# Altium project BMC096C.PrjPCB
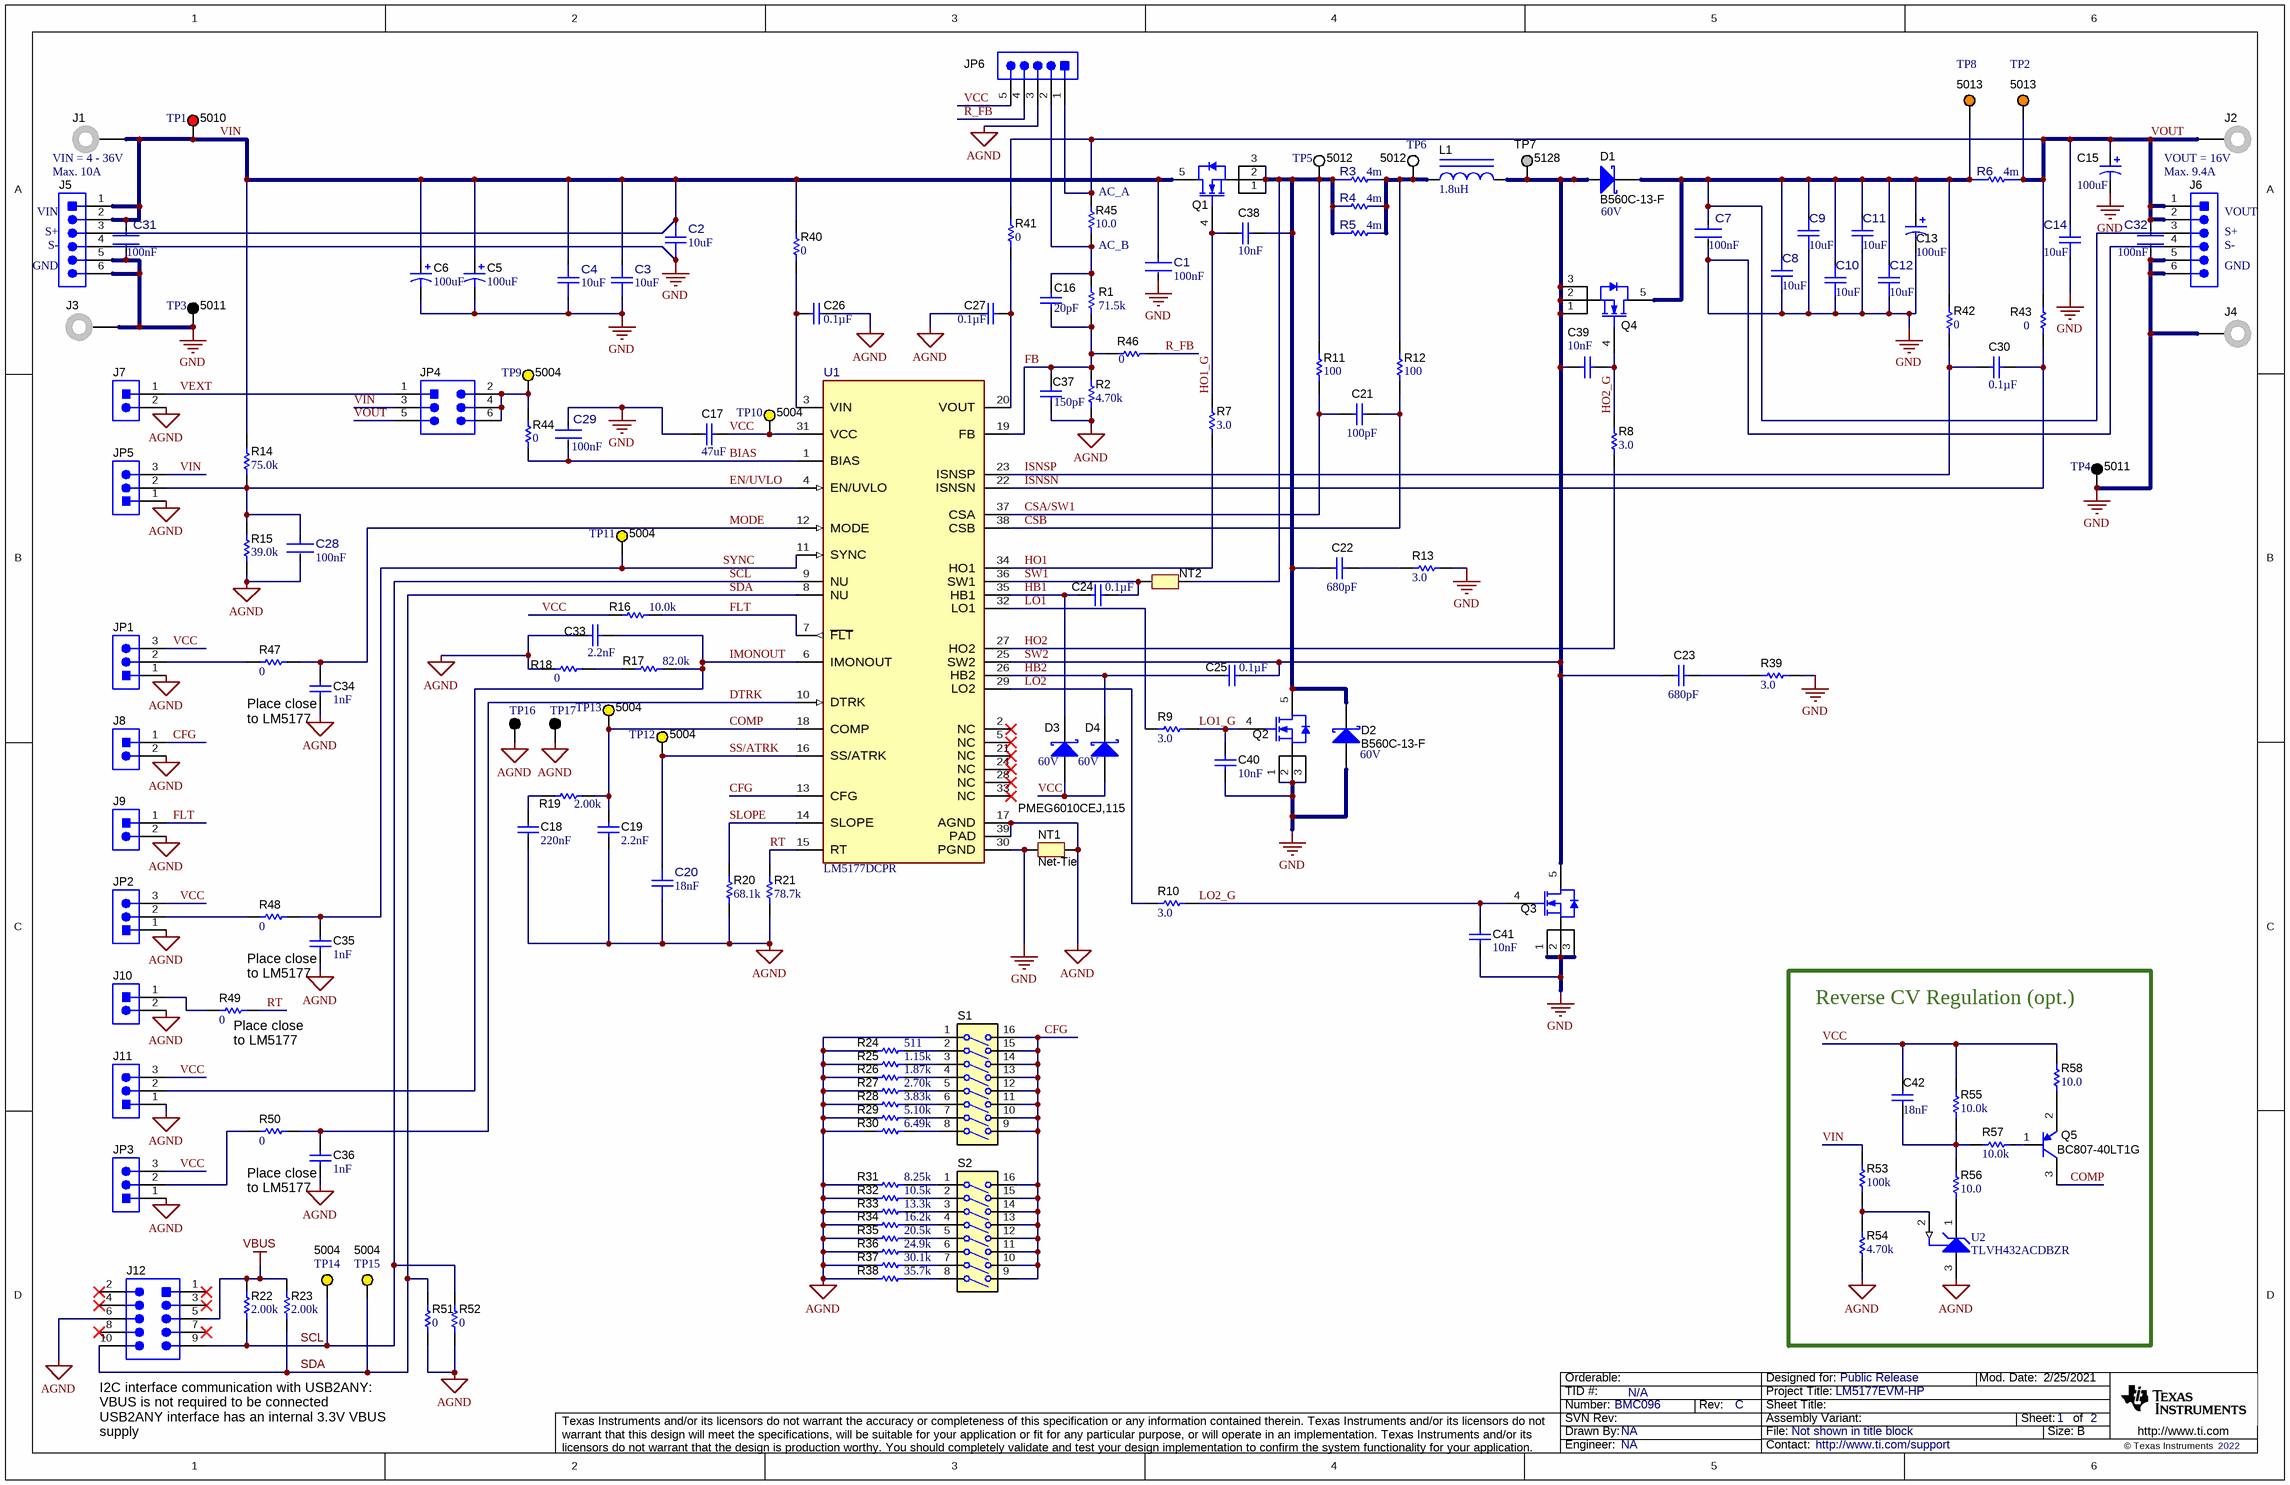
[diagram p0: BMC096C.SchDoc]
TID: N/A; TechSupport: http://www.ti.com/support; SCH_Rev: C; PRJ_Title: LM5177EVM-HP; PRJ_Number: BMC096; PRJ_Engineer: NA; PRJ_Customer: Public Release; PCB_Rev: C; PCB_Layout: NA; CopyrightYear: 2022
2 sheets, 175 parts. Net scope: global (net labels, ports and power ports of the same name join across sheets).
Board file: BMC096C.PcbDoc
Sheets:
  BMC096C.SchDoc
  BMC096C_Hardware.SchDoc

## Sheet BMC096C.SchDoc
size 431 x 279 mm; Date: Not shown in title block; ApprovedBy: Not shown in title block; CheckedBy: Not shown in title block; Author: Not shown in title block; CompanyName: Not shown in title block; DrawnBy: NA; Engineer: Not shown in title block; Organization: Not shown in title block; Address1: Not shown in title block; Address2: Not shown in title block; Address3: Not shown in title block; Address4: Not shown in title block; DocumentNumber: 2; Revision: Use project parameter SCH_Rev; SheetNumber: 1; SheetTotal: 2; PageSetup: Record=PageOptions¦CenterHorizontal=True¦CenterVertical=True¦PrintScale=1.00¦XCorrection=1.00¦YCorrection=1.00¦PrintKind=0¦BorderSize=5000000¦LeftOffset=0¦BottomOffset=0¦Orientation=2¦PaperLength=1000¦PaperWidth=1000¦Scale=100¦PaperSource=15¦PrintQuality=600¦MediaType=1¦DitherType=10¦PaperKind=Letter¦PrintScaleMode=1

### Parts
C1  Cap_F: 100nF  [FP-GCM188L81H104KA57D_0603-MFG]  (hidden comment: GCM188L81H104KA57D)
C2  ValueDisplayed: 10uF  [FP-GCM32EC71H106KA03L_1210-MFG]  (hidden comment: GCM32EC71H106KA03L)
C3  ValueDisplayed: 10uF  [FP-GCM32EC71H106KA03L_1210-MFG]  (hidden comment: GCM32EC71H106KA03L)
C4  ValueDisplayed: 10uF  [FP-GCM32EC71H106KA03L_1210-MFG]  (hidden comment: GCM32EC71H106KA03L)
C5  ValueDisplayed: 100uF  [CR_1000x1270]  (hidden comment: PCR1J101MCL1GS)
C6  ValueDisplayed: 100uF  [CR_1000x1270]  (hidden comment: PCR1J101MCL1GS)
C7  Cap_F: 100nF  [FP-GCM188L81H104KA57D_0603-MFG]  (hidden comment: GCM188L81H104KA57D)
C8  ValueDisplayed: 10uF  [FP-GCM32EC71H106KA03L_1210-MFG]  (hidden comment: GCM32EC71H106KA03L)
C9  ValueDisplayed: 10uF  [FP-GCM32EC71H106KA03L_1210-MFG]  (hidden comment: GCM32EC71H106KA03L)
C10  ValueDisplayed: 10uF  [FP-GCM32EC71H106KA03L_1210-MFG]  (hidden comment: GCM32EC71H106KA03L)
C11  ValueDisplayed: 10uF  [FP-GCM32EC71H106KA03L_1210-MFG]  (hidden comment: GCM32EC71H106KA03L)
C12  ValueDisplayed: 10uF  [FP-GCM32EC71H106KA03L_1210-MFG]  (hidden comment: GCM32EC71H106KA03L)
C13  ValueDisplayed: 100uF  [CR_1000x1270]  (hidden comment: PCR1J101MCL1GS)
C14  ValueDisplayed: 10uF  [FP-GCM32EC71H106KA03L_1210-MFG]  (hidden comment: GCM32EC71H106KA03L)
C15  ValueDisplayed: 100uF  [CR_1000x1270]  (hidden comment: PCR1J101MCL1GS)
C16  ValueDisplayed: 20pF  [0603S]  (hidden comment: GRM1885C2A200JA01D)
C17  ValueDisplayed: 47uF  [0603S]  (hidden comment: GRM188R60J476ME15D)
C18  Cap_F: 220nF  [0603S]  (hidden comment: CGA3E3X7R1H224K080AB)
C19  Cap_F: 2.2nF  [0603S]  (hidden comment: 06031C222JAT2A)
C20  ValueDisplayed: 18nF  [FP-GCM21B5C1H183JA16L_0805-MFG]  (hidden comment: GCM21B5C1H183JA16L)
C21  ValueDisplayed: 100pF  [0603S]  (hidden comment: GCM1885C1H101JA16J)
C22  ValueDisplayed: 680pF  [0805_HV1]  (hidden comment: GRM2165C1H681JA01D)
C23  ValueDisplayed: 680pF  [0805_HV1]  (hidden comment: GRM2165C1H681JA01D)
C24  ValueDisplayed: 0.1µF  [0402S]  (hidden comment: 0402BB104KW500)
C25  ValueDisplayed: 0.1µF  [0402S]  (hidden comment: 0402BB104KW500)
C26  ValueDisplayed: 0.1µF  [0402S]  (hidden comment: 0402BB104KW500)
C27  ValueDisplayed: 0.1µF  [0402S]  (hidden comment: 0402BB104KW500)
C28  Cap_F: 100nF  [FP-GCM188L81H104KA57D_0603-MFG]  (hidden comment: GCM188L81H104KA57D)
C29  Cap_F: 100nF  [FP-GCM188L81H104KA57D_0603-MFG]  (hidden comment: GCM188L81H104KA57D)
C30  ValueDisplayed: 0.1µF  [0402S]  (hidden comment: 0402BB104KW500)
C31  Cap_F: 100nF  [FP-GCM188L81H104KA57D_0603-MFG]  (hidden comment: GCM188L81H104KA57D)
C32  Cap_F: 100nF  [FP-GCM188L81H104KA57D_0603-MFG]  (hidden comment: GCM188L81H104KA57D)
C33  Cap_F: 2.2nF  [0603S]  (hidden comment: 06031C222JAT2A)
C34  Cap_F: 1nF  [0603S]  (hidden comment: 06031C102JAT2A)
C35  Cap_F: 1nF  [0603S]  (hidden comment: 06031C102JAT2A)
C36  Cap_F: 1nF  [0603S]  (hidden comment: 06031C102JAT2A)
C37  ValueDisplayed: 150pF  [0603S]  (hidden comment: GRM1885C1H151JA01D)
C38  Cap_F: 10nF  [0603S]  (hidden comment: GRM188R72A103KA01D)
C39  Cap_F: 10nF  [0603S]  (hidden comment: GRM188R72A103KA01D)
C40  Cap_F: 10nF  [0603S]  (hidden comment: GRM188R72A103KA01D)
C41  Cap_F: 10nF  [0603S]  (hidden comment: GRM188R72A103KA01D)
C42  Cap_F: 18nF  [0603S]  (hidden comment: C0603C183K1RACTU)
D1  B560C-13-F  value 60V  [SMC]
D2  B560C-13-F  value 60V  [SMC]
D3  value 60V  [SOD-323F]  (hidden comment: PMEG6010CEJ,115)
D4  PMEG6010CEJ,115  value 60V  [SOD-323F]
J1  108-0740-001  [Johnson_108-0740-001]  (value not drawn)
J2  108-0740-001  [Johnson_108-0740-001]  (value not drawn)
J3  108-0740-001  [Johnson_108-0740-001]  (value not drawn)
J4  108-0740-001  [Johnson_108-0740-001]  (value not drawn)
J5  61300611121  [WURTH_61300611121]  (value not drawn)
J6  61300611121  [WURTH_61300611121]  (value not drawn)
J7  61300211121  [WURTH_61300211121]  (value not drawn)
J8  61300211121  [WURTH_61300211121]  (value not drawn)
J9  61300211121  [WURTH_61300211121]  (value not drawn)
J10  61300211121  [WURTH_61300211121]  (value not drawn)
J11  61300311121  [WURTH_61300311121]  (value not drawn)
J12  N2510-6002-RB  [CONN_2510-6002]  (value not drawn)
JP1  61300311121  [WURTH_61300311121]  (value not drawn)
JP2  61300311121  [WURTH_61300311121]  (value not drawn)
JP3  61300311121  [WURTH_61300311121]  (value not drawn)
JP4  HTSW-103-07-G-D  [Samtec_HTSW-103-07-x-D]  (value not drawn)
JP5  61300311121  [WURTH_61300311121]  (value not drawn)
JP6  61300511121  [Wurth_61300511121]  (value not drawn)
L1  ValueDisplayed: 1.8uH  [IHLP-5050FD]  (hidden comment: IHLP5050FDER1R8M01)
NT1  Net-Tie  [Net-Tie_10mil]  (net tie, no BOM)
NT2  Net-Tie  [Net-Tie_20milWide_60milLong]  (value not drawn)  (net tie, no BOM)
Q1  SQJ422EP-T1-GE3  [PowerPAK_SO-8L]  (value not drawn)
Q2  SQJ422EP-T1-GE3  [PowerPAK_SO-8L]  (value not drawn)
Q3  SQJ422EP-T1-GE3  [PowerPAK_SO-8L]  (value not drawn)
Q4  SQJ422EP-T1-GE3  [PowerPAK_SO-8L]  (value not drawn)
Q5  BC807-40LT1G  [SOT-23]
R1  ValueDisplayed: 71.5k  [0603S]  (hidden comment: RC0603FR-0771K5L)
R2  ValueDisplayed: 4.70k  [0603S]  (hidden comment: RC0603FR-074K7L)
R3  value 4m  [FP-KRL2012E-M-R004-F-T5_2012-MFG]  (hidden comment: KRL2012E-M-R004-F-T5)
R4  value 4m  [FP-KRL2012E-M-R004-F-T5_2012-MFG]  (hidden comment: KRL2012E-M-R004-F-T5)
R5  value 4m  [FP-KRL2012E-M-R004-F-T5_2012-MFG]  (hidden comment: KRL2012E-M-R004-F-T5)
R6  value 4m  [FP-KRL2012E-M-R004-F-T5_2012-MFG]  (hidden comment: KRL2012E-M-R004-F-T5)
R7  ValueDisplayed: 3.0  [0603S]  (hidden comment: CRCW06033R00JNEA)
R8  ValueDisplayed: 3.0  [0603S]  (hidden comment: CRCW06033R00JNEA)
R9  ValueDisplayed: 3.0  [0603S]  (hidden comment: CRCW06033R00JNEA)
R10  ValueDisplayed: 3.0  [0603S]  (hidden comment: CRCW06033R00JNEA)
R11  ValueDisplayed: 100  [0603S]  (hidden comment: CRCW0603100RFKEAHP)
R12  ValueDisplayed: 100  [0603S]  (hidden comment: CRCW0603100RFKEAHP)
R13  ValueDisplayed: 3.0  [0603S]  (hidden comment: CRCW06033R00JNEA)
R14  ValueDisplayed: 75.0k  [0603S]  (hidden comment: RC0603FR-0775KL)
R15  ValueDisplayed: 39.0k  [0603S]  (hidden comment: RC0603FR-0739KL)
R16  ValueDisplayed: 10.0k  [0603S]  (hidden comment: RT0603BRD0710KL)
R17  ValueDisplayed: 82.0k  [0603S]  (hidden comment: RC0603FR-0782KL)
R18  ValueDisplayed: 0  [0603S]  (hidden comment: RMCF0603ZT0R00)
R19  ValueDisplayed: 2.00k  [0603S]  (hidden comment: RC0603FR-072KL)
R20  ValueDisplayed: 68.1k  [0603S]  (hidden comment: CRCW060368K1FKEA)
R21  ValueDisplayed: 78.7k  [0603S]  (hidden comment: RC0603FR-0778K7L)
R22  ValueDisplayed: 2.00k  [0603S]  (hidden comment: RC0603FR-072KL)
R23  ValueDisplayed: 2.00k  [0603S]  (hidden comment: RC0603FR-072KL)
R24  ValueDisplayed: 511  [0603S]  (hidden comment: CRCW0603511RFKEA)
R25  ValueDisplayed: 1.15k  [0603S]  (hidden comment: CRCW06031K15FKEA)
R26  ValueDisplayed: 1.87k  [0603S]  (hidden comment: RC0603FR-071K87L)
R27  ValueDisplayed: 2.70k  [0603S]  (hidden comment: RC0603FR-072K7L)
R28  ValueDisplayed: 3.83k  [0603S]  (hidden comment: CRCW06033K83FKEA)
R29  ValueDisplayed: 5.10k  [0603S]  (hidden comment: RC0603FR-075K1L)
R30  ValueDisplayed: 6.49k  [0603S]  (hidden comment: RC0603FR-076K49L)
R31  ValueDisplayed: 8.25k  [0603S]  (hidden comment: RC0603FR-078K25L)
R32  ValueDisplayed: 10.5k  [0603S]  (hidden comment: CRCW060310K5FKEA)
R33  ValueDisplayed: 13.3k  [0603S]  (hidden comment: RC0603FR-0713K3L)
R34  ValueDisplayed: 16.2k  [0603S]  (hidden comment: CRCW060316K2FKEA)
R35  ValueDisplayed: 20.5k  [0603S]  (hidden comment: RC0603FR-0720K5L)
R36  ValueDisplayed: 24.9k  [0603S]  (hidden comment: CRCW060324K9FKEA)
R37  ValueDisplayed: 30.1k  [0603S]  (hidden comment: CRCW060330K1FKEA)
R38  ValueDisplayed: 35.7k  [0603S]  (hidden comment: CRCW060335K7FKEA)
R39  ValueDisplayed: 3.0  [0603S]  (hidden comment: CRCW06033R00JNEA)
R40  ValueDisplayed: 0  [0603S]  (hidden comment: RMCF0603ZT0R00)
R41  ValueDisplayed: 0  [0603S]  (hidden comment: RMCF0603ZT0R00)
R42  ValueDisplayed: 0  [0603S]  (hidden comment: RMCF0603ZT0R00)
R43  ValueDisplayed: 0  [0603S]  (hidden comment: RMCF0603ZT0R00)
R44  ValueDisplayed: 0  [0603S]  (hidden comment: RMCF0603ZT0R00)
R45  ValueDisplayed: 10.0  [0603S]  (hidden comment: RC0603FR-0710RL)
R46  ValueDisplayed: 0  [0603S]  (hidden comment: RMCF0603ZT0R00)
R47  ValueDisplayed: 0  [0603S]  (hidden comment: RMCF0603ZT0R00)
R48  ValueDisplayed: 0  [0603S]  (hidden comment: RMCF0603ZT0R00)
R49  ValueDisplayed: 0  [0603S]  (hidden comment: RMCF0603ZT0R00)
R50  ValueDisplayed: 0  [0603S]  (hidden comment: RMCF0603ZT0R00)
R51  ValueDisplayed: 0  [0603S]  (hidden comment: RMCF0603ZT0R00)
R52  ValueDisplayed: 0  [0603S]  (hidden comment: RMCF0603ZT0R00)
R53  ValueDisplayed: 100k  [0603S]  (hidden comment: RC0603FR-07100KL)
R54  ValueDisplayed: 4.70k  [0603S]  (hidden comment: RC0603FR-074K7L)
R55  ValueDisplayed: 10.0k  [0603S]  (hidden comment: CRCW060310K0FKEA)
R56  ValueDisplayed: 10.0  [0603S]  (hidden comment: RC0603FR-0710RL)
R57  ValueDisplayed: 10.0k  [0603S]  (hidden comment: CRCW060310K0FKEA)
R58  ValueDisplayed: 10.0  [0603S]  (hidden comment: RC0603FR-0710RL)
S1  218-8LPST  [SW_218-8LP]  (value not drawn)
S2  218-8LPST  [SW_218-8LP]  (value not drawn)
TP1  5010  [Keystone5010]
TP2  5013  [Keystone5013]
TP3  5011  [Keystone5011]
TP4  5011  [Keystone5011]
TP5  5012  [Keystone5012]
TP6  5012  [Keystone5012]
TP7  5128  [Keystone5128]
TP8  5013  [Keystone5013]
TP9  5004  [Keystone5004]
TP10  5004  [Keystone5004]
TP11  5004  [Keystone5004]
TP12  5004  [Keystone5004]
TP13  5004  [Keystone5004]
TP14  5004  [Keystone5004]
TP15  5004  [Keystone5004]
TP16  5001  [Keystone5001]  (value not drawn)
TP17  5001  [Keystone5001]  (value not drawn)
U1  LM5177DCPR  [DCP0038A-MFG]
U2  TLVH432ACDBZR  [DBZ0003A_N]

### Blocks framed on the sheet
Reverse CV Regulation (opt.): C42 Q5 R53-R58 U2

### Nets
AGND: C18.2 C19.2 C20.1 C26.1 C27.2 C28.2 C33.1 C34.2 C35.2 C36.2 C37.2 J7.2 J8.2 J9.2 J10.2 J11.1 J12.6 JP1.1 JP2.1 JP3.1 JP5.1 JP6.3 NT1.2 R2.1 R15.1 R18.1 R20.1 R21.1 R24.1 R25.1 R26.1 R27.1 R28.1 R29.1 R30.1 R31.1 R32.1 R33.1 R34.1 R35.1 R36.1 R37.1 R38.1 R51.1 R52.1 R54.1 S1.1 TP16.1 TP17.1 U1.17(AGND) U1.39(PAD) U2.3(ANODE)
GND: C1.2 C2.1 C3.1 C4.1 C5.2(-) C6.2(-) C7.2 C8.1 C9.1 C10.1 C11.1 C12.1 C13.2(-) C14.1 C15.2(-) C17.1 C29.1 C31.2 C32.2 C40.1 C41.1 D2.2(A) J3.1 J4.1 J5.4 J5.5 J5.6 J6.4 J6.5 J6.6 NT1.1 Q2.1(S) Q2.2(S) Q2.3(S) Q3.1(S) Q3.2(S) Q3.3(S) R13.1 R39.1 TP3.1 TP4.1 U1.30(PGND)
VBUS: J12.5 R22.2 R23.2
BIAS: C29.2 R44.1 U1.1(BIAS)
CFG: J8.1 S1.9(8A) S1.10(7A) S1.11(6A) S1.12(5A) S1.13(4A) S1.14(3A) S1.15(2A) S1.16(1A) S2.9(8A) S2.10(7A) S2.11(6A) S2.12(5A) S2.13(4A) S2.14(3A) S2.15(2A) S2.16(1A) U1.13(CFG)
COMP: C19.1 Q5.3(C) R19.2 TP13.1 U1.18(COMP)
CSA/SW1: C21.2 R11.1 U1.37(CSA)
CSB: C21.1 R12.1 U1.38(CSB)
DTRK: C36.1 R50.2 U1.10(DTRK)
EN/UVLO: C28.1 JP5.2 R14.1 R15.2 U1.4(EN/UVLO)
FB: C16.2 C37.1 R1.2 R2.2 R46.1 U1.19(FB)
FLT: J9.1 R16.2 U1.7(~{FLT})
HB1: C24.2 D3.1(K) U1.35(HB1)
HB2: C25.2 D4.1(K) U1.26(HB2)
HO1: R7.1 U1.34(HO1)
HO1_G: C38.1 Q1.4(G) R7.2
HO2: R8.1 U1.27(HO2)
HO2_G: C39.2 Q4.4(G) R8.2
IMONOUT: C33.2 J11.2 R17.2 U1.6(IMONOUT)
ISNSN: C30.1 R43.1 U1.22(ISNSN)
ISNSP: C30.2 R42.1 U1.23(ISNSP)
LO1: R9.2 U1.32(LO1)
LO1_G: C40.2 Q2.4(G) R9.1
LO2: R10.2 U1.29(LO2)
LO2_G: C41.2 Q3.4(G) R10.1
MODE: C34.1 R47.2 U1.12(MODE)
R_FB: JP6.4 R46.2
RT: R21.2 R49.1 U1.15(RT)
SCL: J12.9 R22.1 R52.2 TP14.1 U1.9(NU)
SDA: J12.10 R23.1 R51.2 TP15.1 U1.8(NU)
SLOPE: R20.2 U1.14(SLOPE)
SS/ATRK: C20.2 TP12.1 U1.16(SS/ATRK)
SW1: C24.1 NT2.1 U1.36(SW1)
SW2: C23.2 C25.1 C39.1 D1.2(A) L1.2 Q3.5(D) Q4.1(S) Q4.2(S) Q4.3(S) TP7.1 U1.25(SW2)
SYNC: C35.1 R48.2 TP11.1 U1.11(SYNC)
VCC: C17.2 C42.1 D3.2(A) D4.2(A) J11.3 JP1.3 JP2.3 JP3.3 JP6.5 R16.1 R55.2 R58.1 TP10.1 U1.31(VCC)
VEXT: J7.1 JP4.1
VIN: C1.1 C2.2 C3.2 C4.2 C5.1(+) C6.1(+) C31.1 J1.1 J5.1 J5.2 J5.3 JP4.3 JP5.3 Q1.5(D) R14.2 R40.2 R53.2 TP1.1
VOUT: C14.2 C15.1(+) C32.1 J2.1 J6.1 J6.2 JP4.5 JP6.1 R6.2 R41.2 R43.2 R45.2 TP2.1
NetC7_1: C7.1 C8.2 C9.2 C10.2 C11.2 C12.2 C13.1(+) D1.1(K) J6.3 Q4.5(D) R6.1 R42.2 TP8.1
NetC16_1: C16.1 JP6.2 R1.1 R45.1
NetC18_1: C18.1 R19.1
NetC22_1: C22.1 R13.2
NetC22_2: C22.2 C38.2 D2.1(K) NT2.2 Q1.1(S) Q1.2(S) Q1.3(S) Q2.5(D) R3.1 R4.1 R5.1 R11.2 TP5.1
NetC23_1: C23.1 R39.2
NetC26_2: C26.2 R40.1 U1.3(VIN)
NetC27_1: C27.1 R41.1 U1.20(VOUT)
NetC42_2: C42.2 R55.1 R56.2 R57.2
NetJ10_1: J10.1 R49.2
NetJP1_2: JP1.2 R47.1
NetJP2_2: JP2.2 R48.1
NetJP3_2: JP3.2 R50.1
NetJP4_2: JP4.2 JP4.4 JP4.6 R44.2 TP9.1
NetL1_1: L1.1 R3.2 R4.2 R5.2 R12.2 TP6.1
NetQ5_1: Q5.1(B) R57.1
NetQ5_2: Q5.2(E) R58.2
NetR17_1: R17.1 R18.2
NetR24_2: R24.2 S1.2
NetR25_2: R25.2 S1.3
NetR26_2: R26.2 S1.4
NetR27_2: R27.2 S1.5
NetR28_2: R28.2 S1.6
NetR29_2: R29.2 S1.7
NetR30_2: R30.2 S1.8
NetR31_2: R31.2 S2.1
NetR32_2: R32.2 S2.2
NetR33_2: R33.2 S2.3
NetR34_2: R34.2 S2.4
NetR35_2: R35.2 S2.5
NetR36_2: R36.2 S2.6
NetR37_2: R37.2 S2.7
NetR38_2: R38.2 S2.8
NetR53_1: R53.1 R54.2 U2.2(REF)
NetR56_1: R56.1 U2.1(CATHODE)

Not connected (* = marked no-connect by the designer): J12 1* 2* 3* 4* 7* 8*; U1 2(NC)* 5(NC)* 21(NC)* 24(NC)* 28(NC)* 33(NC)*

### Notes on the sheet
- (near J1) VIN = 4 - 36V
- (near J2) VOUT = 16V
- (near J5) VIN
- Max. 10A
- (near R45) AC_A
- Max. 9.4A
- (near J6) VOUT
- (near J5) GND
- (near J5) S+
- (near J5) S-
- (near R45) AC_B
- (near J6) S+
- (near J6) S-
- (near J6) GND
- (near C34) Place close
  to LM5177
- (near C35) Place close
  to LM5177
- (near R49) Place close
  to LM5177
- (near C36) Place close
  to LM5177
- I2C interface communication with USB2ANY:
  VBUS is not required to be connected
  USB2ANY interface has an internal 3.3V VBUS supply

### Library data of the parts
C1 C7 C28 C29 C31 C32 = CMP-0086535-1: 0.1µF ±10% 50V Ceramic Capacitor X8L 0603 (1608 Metric); Manufacturer: Murata Electronics North America; Symbol Name: SYM-GCM188L81H104KA57D; AEC Qualified: Yes; TempCo: -40+15%; SizeZ_mm: 0.9mm; AEC Grade: Grade 0
C2-C4 C8-C12 C14 = CMP-0092251-1: Ceramic Capacitor for Automotive 10uF ±10% 50VDC X7S 1210 Embossed T/R; Manufacturer: Murata; AEC Grade: Grade 1; TempCo: 22%; AEC Qualified: Yes; VDC_V: 50V; Cap_F: 10µF; SizeZ_mm: 2.7mm; Value: 10µF
C5 C6 C13 C15 = CMP-0012274-3: CAP, Aluminum Polymer, 100 uF, 63 V, +/- 20%, 0.024 ohm, SMD, 2-Leads, Dia 10.5mm, Pin Spacing 8mm SMD; Manufacturer: Nichicon; TaMin_C: -55°C; ESR_ohm: 24m; Polarized: Y; Value: 100uF; TaMax_C: 125°C; Cap_Case: 10x12.7mm; Value2: 63V; CompType: Capacitor; AEC Qualified: N; Cap_F: 100µF; IRMS_A: 3A; AEC Category: Q200
C16 = CMP-0007253-4: CAP, CERM, 20 pF, 100 V, +/- 5%, C0G/NP0, 0603; Manufacturer: MuRata; TaMin_C: -55°C; Polarized: N; SizeAreaWB_mm2: 4.68; Value1: Unknown; U/M: EA; Value: 20pF; TaMax_C: 125°C; SizeZ_mm: 1; SizeX_mm: 1.6; SizeY_mm: 0.8; Cap_Case: 0603; Value2: 100V; SizeArea_mm2: 1.28; AEC Category: Q200
C17 = CMP-0007313-5: CAP, CERM, 47 uF, 6.3 V, +/- 20%, X5R, 0603; Manufacturer: MuRata; TaMin_C: -55°C; Polarized: N; SizeAreaWB_mm2: 4.68; Value1: Unknown; U/M: EA; Value: 47uF; TaMax_C: 85°C; SizeZ_mm: 1; SizeX_mm: 1.6; SizeY_mm: 0.8; Cap_Case: 0603; Value2: 6.3V; SizeArea_mm2: 1.28; Cap_F: 47µF; AEC Category: Q200
C18 = CMP-0007094-5: CAP, CERM, 0.22 uF, 50 V, +/- 10%, X7R, AEC-Q200 Grade 1, 0603; Manufacturer: TDK; TaMin_C: -55°C; ESR_ohm: 0.021699; Polarized: N; SizeAreaWB_mm2: 4.68; Value1: 0.021699 ohm; U/M: EA; Value: 0.22uF; TaMax_C: 125°C; SizeZ_mm: 1; SizeX_mm: 1.6; SizeY_mm: 0.8; Cap_Case: 0603; Value2: 50V; SizeArea_mm2: 1.28; AEC Qualified: Y; IRMS_A: 1.12496A; AEC Category: Q200
C19 C33 = CMP-0006736-4: CAP, CERM, 2200 pF, 100 V, +/- 5%, X7R, 0603; Manufacturer: AVX; TaMin_C: -55°C; ESR_ohm: 0.192; Polarized: N; SizeAreaWB_mm2: 4.68; Value1: 0.192 ohm; U/M: EA; Value: 2200pF; TaMax_C: 125°C; SizeZ_mm: 1; SizeX_mm: 1.6; SizeY_mm: 0.8; Cap_Case: 0603; Value2: 100V; SizeArea_mm2: 1.28; AEC Category: Q200
C20 = CMP-0092440-1: Ceramic Capacitor for Automotive 18nF ±5% 50VDC C0G 0805 Embossed T/R; Manufacturer: Murata; TempCo: 30ppm/°C; AEC Qualified: Yes; AEC Grade: Grade 1; VDC_V: 50V; SizeZ_mm: 1.4mm
C21 = CMP-0750041-1: CAP, CERM, 100 pF, 50 V,+/- 5%, C0G/NP0, AEC-Q200 Grade 1, 0603; Manufacturer: MuRata; AEC Grade: 1; SizeArea_mm2: 1.28; SizeX_mm: 1.6; Polarized: N; Cap_Case: 0603; TaMax_C: 125°C; Value2: 50V; Value: 100pF; U/M: EA; AEC Qualified: Y; SizeAreaWB_mm2: 4.68; TaMin_C: -55°C; SizeY_mm: 0.8; AEC Category: Q200
C22 C23 = CMP-0008089-2: CAP, CERM, 680 pF, 50 V, +/- 5%, C0G/NP0, 0805; Manufacturer: MuRata; TaMin_C: -55°C; Polarized: N; SizeAreaWB_mm2: 6.75; Value1: Unknown; U/M: EA; Value: 680pF; TaMax_C: 125°C; SizeZ_mm: 1.45; SizeX_mm: 2; SizeY_mm: 1.25; Cap_Case: 0805; Value2: 50V; SizeArea_mm2: 2.5; AEC Category: Q200
C24-C27 C30 = CMP-0860983-1: CAP, CERM, 0.1 µF, 50 V,+/- 10%, X7R, 0402; Manufacturer: Passive Plus; Cap_Case: 0402; TaMax_C: 125°C; VDC_V: 50V; U/M: EA; SizeY_mm: 0.5; TaMin_C: -55°C; SizeAreaWB_mm2: 3; Value: 0.1uF; AEC Qualified: N; SizeX_mm: 1; AEC Category: Q200; SizeZ_mm: 0.6; Cap_F: 100nF
C34-C36 = CMP-0006723-4: CAP, CERM, 1000 pF, 100 V, +/- 5%, X7R, 0603; Manufacturer: AVX; TaMin_C: -55°C; ESR_ohm: 2.76d; Polarized: N; SizeAreaWB_mm2: 4.68; Value1: 0.276 ohm; U/M: EA; Value: 1000pF; TaMax_C: 125°C; SizeZ_mm: 1; SizeX_mm: 1.6; SizeY_mm: 0.8; Cap_Case: 0603; Value2: 100V; SizeArea_mm2: 1.28; AEC Category: Q200
C37 = CMP-0007185-4: CAP, CERM, 150 pF, 50 V, +/- 5%, C0G/NP0, 0603; Manufacturer: MuRata; TaMin_C: -55°C; Polarized: N; SizeAreaWB_mm2: 4.68; Value1: Unknown; U/M: EA; Value: 150pF; TaMax_C: 125°C; SizeZ_mm: 1; SizeX_mm: 1.6; SizeY_mm: 0.8; Cap_Case: 0603; Value2: 50V; SizeArea_mm2: 1.28; AEC Category: Q200
C38-C41 = CMP-0007468-5: CAP, CERM, 0.01 uF, 100 V, +/- 10%, X7R, 0603; Manufacturer: MuRata; TaMin_C: -55°C; Polarized: N; SizeAreaWB_mm2: 4.68; Value1: Unknown; U/M: EA; Value: 0.01uF; TaMax_C: 125°C; SizeZ_mm: 1; SizeX_mm: 1.6; SizeY_mm: 0.8; Cap_Case: 0603; Value2: 100V; SizeArea_mm2: 1.28; AEC Category: Q200
C42 = CMP-0006889-4: CAP, CERM, 0.018 uF, 100 V, +/- 10%, X7R, 0603; Manufacturer: Kemet; TaMin_C: -55°C; Polarized: N; SizeAreaWB_mm2: 4.68; Value1: Unknown; U/M: EA; TaMax_C: 125°C; SizeZ_mm: 1; SizeX_mm: 1.6; SizeY_mm: 0.8; Cap_Case: 0603; Value2: 100V; SizeArea_mm2: 1.28; AEC Category: Q200
D1 D2 = CMP-0028433-2: Diode, Schottky, 60 V, 5 A, SMC; Manufacturer: Diodes Inc.; Io_A: 5A; Green_Lifecycle: Active; SizeAreaWB_mm2: 83.2686; Green_REACh: Passed; TJmax_C: 125°C; SizeZ_mm: 2.6; SizeX_mm: 8.13; SizeY_mm: 6.22; Vf_V: 700mV; Value2: 0.7V; SizeArea_mm2: 50.5686; AEC Category: Q101; RJC_CperW: 10
D3 D4 = CMP-0077011-2: Diode, Schottky, 60 V, 1 A, SOD-323F; Manufacturer: Nexperia; SizeX_mm: 2.5; TJmax_C: 150°C; SizeZ_mm: 0.8; Green_Lifecycle: Not Set; Value2: 0.66V; SizeAreaWB_mm2: 7.875; Green_REACh: Incomplete; Io_A: 1A; SizeY_mm: 1.25; SizeArea_mm2: 3.125; Vf_V: 660mV; AEC Category: Q101
J1-J4 = CMP-0055387-2: Standard Banana Jack, Uninsulated, 15A; Manufacturer: Cinch Connectivity; CNHeader: FALSE; Green_Lifecycle: Active; Green_REACh: Passed; CT: TRUE
J5 J6 = CMP-0054801-2: Header, 2.54 mm, 6x1, Gold, TH; Manufacturer: Wurth Elektronik; Cert_UL: Y; Gender: Male; Row_Count: 1; Shrouded: N; Pitch_mm: 2.54
J7-J10 = CMP-0054794-2: Header, 2.54 mm, 2x1, Gold, TH; Manufacturer: Wurth Elektronik; Shrouded: N; Gender: Male; Green_REACh: Passed; Pitch_mm: 2.54; Green_Lifecycle: Active; Row_Count: 1; Cert_UL: Y
J11 JP1-JP3 JP5 = CMP-0054796-4: Header, 2.54 mm, 3x1, Gold, TH; Manufacturer: Wurth Elektronik; Green_Lifecycle: Active; Green_REACh: Passed; CT: FALSE; CNHeader: TRUE
J12 = CMP-0055448-2: Header (shrouded), 100mil, 5x2, High-Temperature, Gold, TH; Manufacturer: 3M; Green_Lifecycle: Active; Green_REACh: Passed
JP4 = CMP-0055587-2: Header, 2.54mm, 3x2, Gold, TH; Manufacturer: Samtec; Green_Lifecycle: Active; Shrouded: N; Gender: Male; Cert_CSA: Y; Green_REACh: Passed; Row_Count: 2; RowSpacing_mm: 2.54
JP6 = CMP-0084909-1: Header, 2.54mm, 5x1, Gold, TH; Manufacturer: Wurth Elektronik; Pitch_mm: 2.54; Current_A: 3A; Shrouded: N; Gender: Male; Voltage_V: 250V; Row_Count: 1
L1 = CMP-0063502-1: Inductor, Shielded, Powdered Iron, 1.8 uH, 24 A, 0.0032 ohm, SMD; Manufacturer: Vishay-Dale; Isat: 41A @ 20% inductance drop; Irms: 24A @ 40C rise; Green_Lifecycle: Active; SizeAreaWB_mm2: 226.48; DCR_ohm: 3.2m; Green_REACh: Passed; Value: 1.8uH; Imax_A: 24A; SizeZ_mm: 6.5; SizeX_mm: 13.2; SizeY_mm: 12.9; SizeArea_mm2: 170.28; Ind_H: 1.8µH; AEC Category: Q200
NT1 NT2 = CMP-0078142-6: Single point connection between nets.
Q1-Q4 = CMP-0000747-1: MOSFET, N-CH, 40 V, 75 A, PowerPAK_SO-8L; Alternate Manufacturer: None; Manufacturer: Vishay-Siliconix; SizeZ_mm: 1.14; ChType: N; Value2: 67 nC; Value1: 0.004; VdsMax_V: 40V; SizeX_mm: 6.15; SizeY_mm: 5.13; Vgs_V: 20V; Value: 40V; Rdson45_ohm: 4.3m; SizeArea_mm2: 31.5495; AEC Category: Q101; IdsMax_A: 75A; SizeAreaWB_mm2: 58.1095; U/M: EA; QgTyp_nC: 67
Q5 = CMP-0000367-2: Transistor, PNP, 45 V, 0.5 A, AEC-Q101, SOT-23; Manufacturer: ON Semiconductor; TaMax_C: 150°C; Value2: 600; Value1: 0.5 A; Vcesat1_V: 700mV; SizeX_mm: 2.5; SizeY_mm: 3; TaMin_C: -55°C; IcRated_A: 500mA; CompType: BJT; SizeZ_mm: 1.1; AEC Qualified: Y; Value: 45 V; SizeArea_mm2: 7.5; NPN: 0; Vceo_V: 45V; PNP: 1; AEC Category: Q101; SizeAreaWB_mm2: 14; U/M: EA
R1 = CMP-0023259-5: RES, 71.5 k, 1%, 0.1 W, 0603; Manufacturer: Yageo; Power_W: 100mW; TempCo: 100 ppm/C; Value_Code: 71k5; Value: 71.5k; EIA_Code: E96; SizeX_mm: 1.6; SizeY_mm: 0.8; SizeZ_mm: 1; Value2: 0.1W; SizeArea_mm2: 1.28; AEC Qualified: N; VDC_V: 75V; AEC Category: Q200; SizeAreaWB_mm2: 4.68
R2 R54 = CMP-0023153-5: RES, 4.70 k, 1%, 0.1 W, 0603; Manufacturer: Yageo; Power_W: 100mW; TempCo: 100 ppm/C; Value_Code: 4k70; Value: 4.70k; Res_ohm: 4.7k; SizeX_mm: 1.6; SizeY_mm: 0.8; SizeZ_mm: 1; Value2: 0.1W; SizeArea_mm2: 1.28; AEC Qualified: N; VDC_V: 75V; AEC Category: Q200; SizeAreaWB_mm2: 4.68
R3-R6 = CMP-0090660-1: 4 mOhms ±1% 1W Chip Resistor Wide 0805 (2012 Metric), 0508 Automotive AEC-Q200, Current Sense Metal Foil; Manufacturer: Susumu; AEC Grade: Grade 0; TempCo: 50ppm/°C; SizeZ_mm: 0.7mm; AEC Qualified: Yes
R7-R10 R13 R39 = CMP-0025804-4: RES, 3.0, 5%, 0.1 W, AEC-Q200 Grade 0, 0603; Manufacturer: Vishay-Dale; Power_W: 100mW; TempCo: 200 ppm/C; Value_Code: 3R00; Value: 3.0; EIA_Code: E24; Res_ohm: 3; SizeX_mm: 1.6; SizeY_mm: 0.8; SizeZ_mm: 1; Value2: 0.1W; SizeArea_mm2: 1.28; AEC Qualified: Y; VDC_V: 75V; AEC Category: Q200; AEC Grade: 0
R11 R12 = CMP-0084243-1: RES, 100, 1%, 0.25 W, AEC-Q200 Grade 0, 0603; Manufacturer: Vishay-Dale; Power_W: 250mW; TempCo: 100 ppm/C; SizeAreaWB_mm2: 4.68; Value_Code: 100R; Value: 100; EIA_Code: E96; SizeX_mm: 1.6; SizeY_mm: 0.8; SizeZ_mm: 1; Value2: 0.25W; SizeArea_mm2: 1.28; AEC Qualified: Y; AEC Grade: 0; AEC Category: Q200
R14 = CMP-0023267-5: RES, 75.0 k, 1%, 0.1 W, 0603; Manufacturer: Yageo; Power_W: 100mW; TempCo: 100 ppm/C; Value_Code: 75k0; Value: 75.0k; EIA_Code: E96; Res_ohm: 75k; SizeX_mm: 1.6; SizeY_mm: 0.8; SizeZ_mm: 1; Value2: 0.1W; SizeArea_mm2: 1.28; AEC Qualified: N; VDC_V: 75V; AEC Category: Q200; SizeAreaWB_mm2: 4.68
R15 = CMP-0023073-5: RES, 39.0 k, 1%, 0.1 W, 0603; Manufacturer: Yageo; Power_W: 100mW; TempCo: 100 ppm/C; Value_Code: 39k0; Value: 39.0k; Res_ohm: 39k; SizeX_mm: 1.6; SizeY_mm: 0.8; SizeZ_mm: 1; Value2: 0.1W; SizeArea_mm2: 1.28; AEC Qualified: N; VDC_V: 75V; AEC Category: Q200; SizeAreaWB_mm2: 4.68
R16 = CMP-0023653-3: RES, 10.0 k, 0.1%, 0.1 W, 0603; Manufacturer: Yageo America; Power_W: 100mW; TempCo: 25 ppm/C; Value_Code: 10k0; U/M: EA; Value: 10.0k; EIA_Code: E192; Res_ohm: 10k; SizeX_mm: 1.6; SizeY_mm: 0.8; SizeZ_mm: 1; Value2: 0.1W; SizeArea_mm2: 1.28; VDC_V: 75V; AEC Category: Q200
R17 = CMP-0023292-5: RES, 82.0 k, 1%, 0.1 W, 0603; Manufacturer: Yageo; Power_W: 100mW; TempCo: 100 ppm/C; Value_Code: 82k0; Value: 82.0k; Res_ohm: 82k; SizeX_mm: 1.6; SizeY_mm: 0.8; SizeZ_mm: 1; Value2: 0.1W; SizeArea_mm2: 1.28; AEC Qualified: N; VDC_V: 75V; AEC Category: Q200; SizeAreaWB_mm2: 4.68
R18 R40-R44 R46-R52 = CMP-0023343-3: RES, 0, 1%, 0.1 W, AEC-Q200 Grade 0, 0603; Manufacturer: Stackpole Electronics Inc; Power_W: 100mW; TempCo: ppm/C; U/M: EA; Value: 0; SizeX_mm: 1.6; SizeY_mm: 0.8; SizeZ_mm: 1; Value2: 0.1W; SizeArea_mm2: 1.28; AEC Qualified: Y; AEC Category: Q200
R19 R22 R23 = CMP-0023000-5: RES, 2.00 k, 1%, 0.1 W, 0603; Manufacturer: Yageo; Power_W: 100mW; TempCo: 100 ppm/C; Value_Code: 2k00; Value: 2.00k; EIA_Code: E96; Res_ohm: 2k; SizeX_mm: 1.6; SizeY_mm: 0.8; SizeZ_mm: 1; Value2: 0.1W; SizeArea_mm2: 1.28; AEC Qualified: N; VDC_V: 75V; AEC Category: Q200; SizeAreaWB_mm2: 4.68
R20 = CMP-0022552-4: RES, 68.1 k, 1%, 0.1 W, AEC-Q200 Grade 0, 0603; Manufacturer: Vishay-Dale; Power_W: 100mW; TempCo: 100 ppm/C; Value_Code: 68k1; Value: 68.1k; EIA_Code: E96; SizeX_mm: 1.6; SizeY_mm: 0.8; SizeZ_mm: 1; Value2: 0.1W; SizeArea_mm2: 1.28; AEC Qualified: Y; VDC_V: 75V; AEC Category: Q200; AEC Grade: 0
R21 = CMP-0023275-5: RES, 78.7 k, 1%, 0.1 W, 0603; Manufacturer: Yageo; Power_W: 100mW; TempCo: 100 ppm/C; Value_Code: 78k7; Value: 78.7k; EIA_Code: E96; SizeX_mm: 1.6; SizeY_mm: 0.8; SizeZ_mm: 1; Value2: 0.1W; SizeArea_mm2: 1.28; AEC Qualified: N; VDC_V: 75V; AEC Category: Q200; SizeAreaWB_mm2: 4.68
R24 = CMP-0022481-5: RES, 511, 1%, 0.1 W, AEC-Q200 Grade 0, 0603; Manufacturer: Vishay-Dale; Power_W: 100mW; TempCo: 100 ppm/C; Value_Code: 511R; Value: 511; EIA_Code: E96; SizeX_mm: 1.6; SizeY_mm: 0.8; SizeZ_mm: 1; Value2: 0.1W; SizeArea_mm2: 1.28; AEC Qualified: Y; VDC_V: 75V; AEC Category: Q200; AEC Grade: 0
R25 = CMP-0022115-4: RES, 1.15 k, 1%, 0.1 W, AEC-Q200 Grade 0, 0603; Manufacturer: Vishay-Dale; Power_W: 100mW; TempCo: 100 ppm/C; Value_Code: 1k15; Value: 1.15k; EIA_Code: E96; SizeX_mm: 1.6; SizeY_mm: 0.8; SizeZ_mm: 1; Value2: 0.1W; SizeArea_mm2: 1.28; AEC Qualified: Y; VDC_V: 75V; AEC Category: Q200; AEC Grade: 0
R26 = CMP-0022891-5: RES, 1.87 k, 1%, 0.1 W, 0603; Manufacturer: Yageo; Power_W: 100mW; TempCo: 100 ppm/C; Value_Code: 1k87; Value: 1.87k; EIA_Code: E96; SizeX_mm: 1.6; SizeY_mm: 0.8; SizeZ_mm: 1; Value2: 0.1W; SizeArea_mm2: 1.28; AEC Qualified: N; VDC_V: 75V; AEC Category: Q200; SizeAreaWB_mm2: 4.68
R27 = CMP-0022996-5: RES, 2.70 k, 1%, 0.1 W, 0603; Manufacturer: Yageo; Power_W: 100mW; TempCo: 100 ppm/C; Value_Code: 2k70; Value: 2.70k; Res_ohm: 2.7k; SizeX_mm: 1.6; SizeY_mm: 0.8; SizeZ_mm: 1; Value2: 0.1W; SizeArea_mm2: 1.28; AEC Qualified: N; VDC_V: 75V; AEC Category: Q200; SizeAreaWB_mm2: 4.68
R28 = CMP-0022381-4: RES, 3.83 k, 1%, 0.1 W, AEC-Q200 Grade 0, 0603; Manufacturer: Vishay-Dale; Power_W: 100mW; TempCo: 100 ppm/C; Value_Code: 3k83; Value: 3.83k; EIA_Code: E96; SizeX_mm: 1.6; SizeY_mm: 0.8; SizeZ_mm: 1; Value2: 0.1W; SizeArea_mm2: 1.28; AEC Qualified: Y; VDC_V: 75V; AEC Category: Q200; AEC Grade: 0
R29 = CMP-0023198-5: RES, 5.10 k, 1%, 0.1 W, 0603; Manufacturer: Yageo; Power_W: 100mW; TempCo: 100 ppm/C; Value_Code: 5k10; Value: 5.10k; Res_ohm: 5.1k; SizeX_mm: 1.6; SizeY_mm: 0.8; SizeZ_mm: 1; Value2: 0.1W; SizeArea_mm2: 1.28; AEC Qualified: N; VDC_V: 75V; AEC Category: Q200; SizeAreaWB_mm2: 4.68
R30 = CMP-0023250-5: RES, 6.49 k, 1%, 0.1 W, 0603; Manufacturer: Yageo; Power_W: 100mW; TempCo: 100 ppm/C; Value_Code: 6k49; Value: 6.49k; EIA_Code: E96; SizeX_mm: 1.6; SizeY_mm: 0.8; SizeZ_mm: 1; Value2: 0.1W; SizeArea_mm2: 1.28; AEC Qualified: N; VDC_V: 75V; AEC Category: Q200; SizeAreaWB_mm2: 4.68
R31 = CMP-0023307-5: RES, 8.25 k, 1%, 0.1 W, 0603; Manufacturer: Yageo; Power_W: 100mW; TempCo: 100 ppm/C; Value_Code: 8k25; Value: 8.25k; EIA_Code: E96; SizeX_mm: 1.6; SizeY_mm: 0.8; SizeZ_mm: 1; Value2: 0.1W; SizeArea_mm2: 1.28; AEC Qualified: N; VDC_V: 75V; AEC Category: Q200; SizeAreaWB_mm2: 4.68
R32 = CMP-0022000-4: RES, 10.5 k, 1%, 0.1 W, AEC-Q200 Grade 0, 0603; Manufacturer: Vishay-Dale; Power_W: 100mW; TempCo: 100 ppm/C; Value_Code: 10k5; Value: 10.5k; EIA_Code: E96; SizeX_mm: 1.6; SizeY_mm: 0.8; SizeZ_mm: 1; Value2: 0.1W; SizeArea_mm2: 1.28; AEC Qualified: Y; VDC_V: 75V; AEC Category: Q200; AEC Grade: 0
R33 = CMP-0022790-5: RES, 13.3 k, 1%, 0.1 W, 0603; Manufacturer: Yageo; Power_W: 100mW; TempCo: 100 ppm/C; Value_Code: 13k3; Value: 13.3k; EIA_Code: E96; SizeX_mm: 1.6; SizeY_mm: 0.8; SizeZ_mm: 1; Value2: 0.1W; SizeArea_mm2: 1.28; AEC Qualified: N; VDC_V: 75V; AEC Category: Q200; SizeAreaWB_mm2: 4.68
R34 = CMP-0022079-4: RES, 16.2 k, 1%, 0.1 W, AEC-Q200 Grade 0, 0603; Manufacturer: Vishay-Dale; Power_W: 100mW; TempCo: 100 ppm/C; Value_Code: 16k2; Value: 16.2k; EIA_Code: E96; SizeX_mm: 1.6; SizeY_mm: 0.8; SizeZ_mm: 1; Value2: 0.1W; SizeArea_mm2: 1.28; AEC Qualified: Y; VDC_V: 75V; AEC Category: Q200; AEC Grade: 0
R35 = CMP-0022905-5: RES, 20.5 k, 1%, 0.1 W, 0603; Manufacturer: Yageo; Power_W: 100mW; TempCo: 100 ppm/C; Value_Code: 20k5; Value: 20.5k; EIA_Code: E96; SizeX_mm: 1.6; SizeY_mm: 0.8; SizeZ_mm: 1; Value2: 0.1W; SizeArea_mm2: 1.28; AEC Qualified: N; VDC_V: 75V; AEC Category: Q200; SizeAreaWB_mm2: 4.68
R36 = CMP-0022237-4: RES, 24.9 k, 1%, 0.1 W, AEC-Q200 Grade 0, 0603; Manufacturer: Vishay-Dale; Power_W: 100mW; TempCo: 100 ppm/C; Value_Code: 24k9; Value: 24.9k; EIA_Code: E96; SizeX_mm: 1.6; SizeY_mm: 0.8; SizeZ_mm: 1; Value2: 0.1W; SizeArea_mm2: 1.28; AEC Qualified: Y; VDC_V: 75V; AEC Category: Q200; AEC Grade: 0
R37 = CMP-0022324-4: RES, 30.1 k, 1%, 0.1 W, AEC-Q200 Grade 0, 0603; Manufacturer: Vishay-Dale; Power_W: 100mW; TempCo: 100 ppm/C; Value_Code: 30k1; Value: 30.1k; EIA_Code: E96; SizeX_mm: 1.6; SizeY_mm: 0.8; SizeZ_mm: 1; Value2: 0.1W; SizeArea_mm2: 1.28; AEC Qualified: Y; VDC_V: 75V; AEC Category: Q200; AEC Grade: 0
R38 = CMP-0022352-4: RES, 35.7 k, 1%, 0.1 W, AEC-Q200 Grade 0, 0603; Manufacturer: Vishay-Dale; Power_W: 100mW; TempCo: 100 ppm/C; Value_Code: 35k7; Value: 35.7k; EIA_Code: E96; SizeX_mm: 1.6; SizeY_mm: 0.8; SizeZ_mm: 1; Value2: 0.1W; SizeArea_mm2: 1.28; AEC Qualified: Y; VDC_V: 75V; AEC Category: Q200; AEC Grade: 0
R45 R56 R58 = CMP-0022751-4: RES, 10.0, 1%, 0.1 W, 0603; Manufacturer: Yageo; Power_W: 100mW; TempCo: 100 ppm/C; Value_Code: 10R0; Value: 10.0; EIA_Code: E96; Res_ohm: 10; SizeX_mm: 1.6; SizeY_mm: 0.8; SizeZ_mm: 1; Value2: 0.1W; SizeArea_mm2: 1.28; AEC Qualified: N; VDC_V: 75V; AEC Category: Q200; SizeAreaWB_mm2: 4.68
R53 = CMP-0022735-5: RES, 100 k, 1%, 0.1 W, 0603; Manufacturer: Yageo; Power_W: 100mW; TempCo: 100 ppm/C; Value: 100k; EIA_Code: E96; SizeX_mm: 1.6; SizeY_mm: 0.8; SizeZ_mm: 1; Value2: 0.1W; SizeArea_mm2: 1.28; AEC Qualified: N; VDC_V: 75V; AEC Category: Q200; SizeAreaWB_mm2: 4.68
R55 R57 = CMP-0021998-4: RES, 10.0 k, 1%, 0.1 W, AEC-Q200 Grade 0, 0603; Manufacturer: Vishay-Dale; Power_W: 100mW; TempCo: 100 ppm/C; Value_Code: 10k0; Value: 10.0k; EIA_Code: E96; Res_ohm: 10k; SizeX_mm: 1.6; SizeY_mm: 0.8; SizeZ_mm: 1; Value2: 0.1W; SizeArea_mm2: 1.28; AEC Qualified: Y; VDC_V: 75V; AEC Category: Q200; AEC Grade: 0
S1 S2 = CMP-0002229-1: Switch, SPST, 8 Pos, 25mA, 24VDC, SMD; Manufacturer: CTS Electrocomponents; CurrentRating_mA: 25A; PositionCount: 8; VDC_V: 24V; SwitchFunction: Off-On
TP1 = CMP-0055147-2: Test Point, Multipurpose, Red, TH; Manufacturer: Keystone Electronics; CNHeader: FALSE; Green_Lifecycle: Active; Green_REACh: Passed; ContactFinish: Silver; CT: TRUE
TP2 TP8 = CMP-0055150-2: Test Point, Multipurpose, Orange, TH; Manufacturer: Keystone Electronics; CNHeader: FALSE; Green_Lifecycle: Active; Green_REACh: Passed; ContactFinish: Silver; CT: TRUE
TP3 TP4 = CMP-0055148-2: Test Point, Multipurpose, Black, TH; Manufacturer: Keystone Electronics; CNHeader: FALSE; Green_Lifecycle: Active; Green_REACh: Passed; ContactFinish: Silver; CT: TRUE
TP5 TP6 = CMP-0055149-2: Test Point, Multipurpose, White, TH; Manufacturer: Keystone Electronics; CNHeader: FALSE; Green_Lifecycle: Active; Green_REACh: Passed; ContactFinish: Silver; CT: TRUE
TP7 = CMP-0055159-2: Test Point, Multipurpose, Grey, TH; Manufacturer: Keystone Electronics; CNHeader: FALSE; Green_Lifecycle: Active; Green_REACh: Passed; ContactFinish: Silver; CT: TRUE
TP9-TP15 = CMP-0055141-2: Test Point, Miniature, Yellow, TH; Manufacturer: Keystone Electronics; CNHeader: FALSE; Green_Lifecycle: Active; Green_REACh: Passed; ContactFinish: Silver; CT: TRUE
TP16 TP17 = CMP-0055138-2: Test Point, Miniature, Black, TH; Manufacturer: Keystone Electronics; CNHeader: FALSE; Green_Lifecycle: Active; Green_REACh: Passed; ContactFinish: Silver; CT: TRUE
U1 = CMP-0094661-2: Wide VIN Bidirectional 4 Switch Buck-Boost Controller; Manufacturer: Texas Instruments; Output Voltage: 3.3-78V; Max Supply Voltage: 78V; AEC Qualified: No; SizeZ_mm: 1.2mm; Switching Frequency: 100-2000kHz; AEC Category: Q200; Number Of Outputs: 2; Min Supply Voltage: 2.8V; Output Type: AdjustableProgrammable; Max Duty Cycle: 100%; CompType: IC; Standoff Height: 0.05mm; Nominal Supply Current: 25uA; TJmax_C: +125°C
U2 = CMP-0032992-1: Low-Voltage Adjustable Precision Shunt Regulator, 129 ppm / degC, 80 mA, 0 to 70 degC, 3-pin SOT-23 (DBZ), Green (RoHS & no Sb/Br); Manufacturer: Texas Instruments; VO Adj(Max)(V): 18; Initial Accuracy @ 25/deg C(%): 1; Min Iz for Regulation(uA): 80; Temp Coeff(Max)(ppm/ degree C): 129; VO Adj(Min)(V): 1.24; Rating: Catalog; SubFamily: Shunt Voltage Reference

## Sheet BMC096C_Hardware.SchDoc
size 431 x 279 mm; Date: Not shown in title block; ApprovedBy: Not shown in title block; CheckedBy: Not shown in title block; Author: Not shown in title block; CompanyName: Not shown in title block; DrawnBy: NA; Engineer: Not shown in title block; Organization: Not shown in title block; Address1: Not shown in title block; Address2: Not shown in title block; Address3: Not shown in title block; Address4: Not shown in title block; DocumentNumber: 3; Revision: Use project parameter SCH_Rev; SheetNumber: 2; SheetTotal: 2; PageSetup: Record=PageOptions¦CenterHorizontal=True¦CenterVertical=True¦PrintScale=1.00¦XCorrection=1.00¦YCorrection=1.00¦PrintKind=0¦BorderSize=5000000¦LeftOffset=0¦BottomOffset=0¦Orientation=2¦PaperLength=1000¦PaperWidth=1000¦Scale=100¦PaperSource=15¦PrintQuality=600¦MediaType=1¦DitherType=10¦PaperKind=Letter¦PrintScaleMode=1
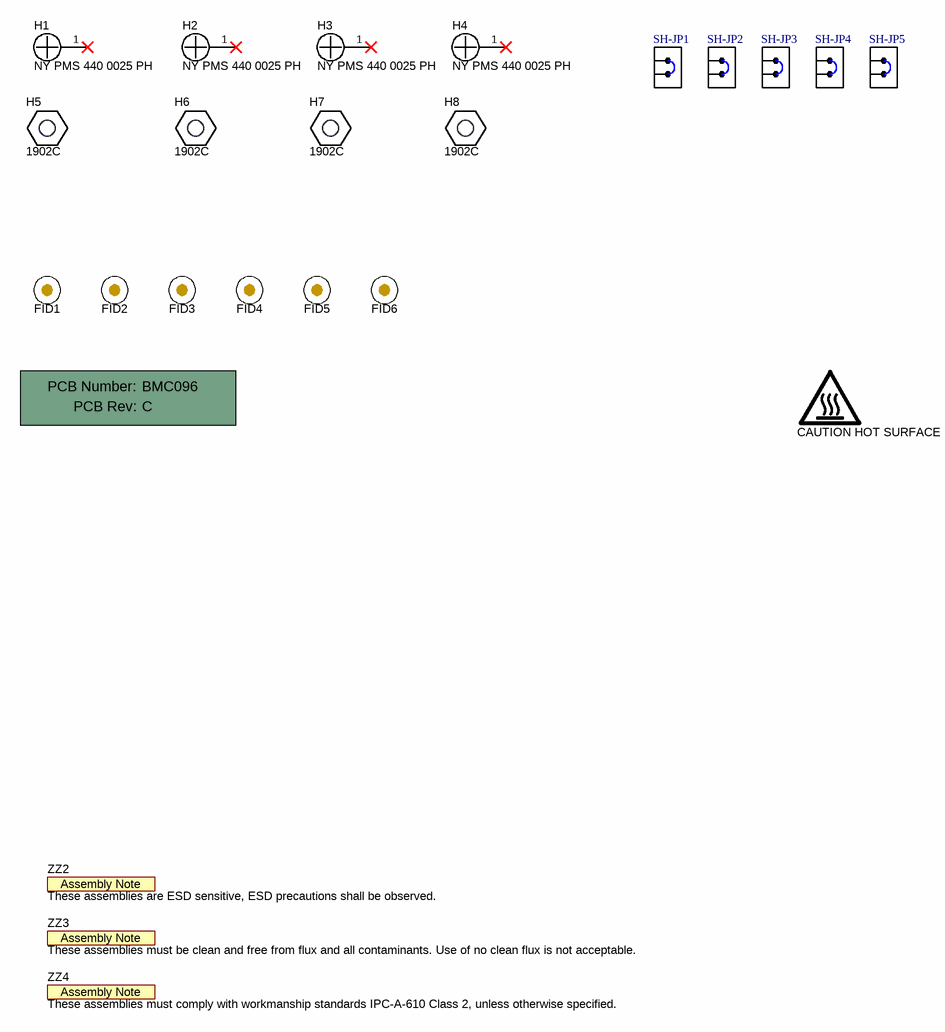
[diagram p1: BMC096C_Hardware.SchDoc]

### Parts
!PCB  Printed Circuit Board  (value not drawn)  (mechanical)
FID1  Fiducial  [Fiducial10-20]  (value not drawn)
FID2  Fiducial  [Fiducial10-20]  (value not drawn)
FID3  Fiducial  [Fiducial10-20]  (value not drawn)
FID4  Fiducial  [Fiducial10-20]  (value not drawn)
FID5  Fiducial  [Fiducial10-20]  (value not drawn)
FID6  Fiducial  [Fiducial10-20]  (value not drawn)
H1  NY PMS 440 0025 PH  [NY PMS 440 0025 PH]
H2  NY PMS 440 0025 PH  [NY PMS 440 0025 PH]
H3  NY PMS 440 0025 PH  [NY PMS 440 0025 PH]
H4  NY PMS 440 0025 PH  [NY PMS 440 0025 PH]
H5  1902C  [Keystone_1902C]
H6  1902C  [Keystone_1902C]
H7  1902C  [Keystone_1902C]
H8  1902C  [Keystone_1902C]
Logo5  CAUTION HOT SURFACE  [IEC_HotSurface_Small]  (no BOM)
SH-JP1  M7582-05  [Harwin_M7582-05]  (value not drawn)
SH-JP2  M7582-05  [Harwin_M7582-05]  (value not drawn)
SH-JP3  M7582-05  [Harwin_M7582-05]  (value not drawn)
SH-JP4  M7582-05  [Harwin_M7582-05]  (value not drawn)
SH-JP5  M7582-05  [Harwin_M7582-05]  (value not drawn)
ZZ2  These assemblies are ESD sensitive, ESD precautions shall be observed.  [AssemblyNote]  (no BOM)
ZZ3  These assemblies must be clean and free from flux and all contaminants. Use of no clean flux is not acceptable.  [AssemblyNote]  (no BOM)
ZZ4  These assemblies must comply with workmanship standards IPC-A-610 Class 2, unless otherwise specified.  [AssemblyNote]  (no BOM)

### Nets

Not connected (* = marked no-connect by the designer): H1 1*; H2 1*; H3 1*; H4 1*

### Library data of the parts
!PCB = CMP-0003618-2: Manufacturer: Any; PartNumber: BMC096
FID1-FID6 = CMP-0077181-1: Fiducial mark.  There is nothing to buy or mount.
H1-H4 = CMP-0003617-1: Machine Screw, Round, #4-40 x 1/4, Nylon, Philips panhead; Manufacturer: B&F Fastener Supply; CompType: Hardware
H5-H8 = CMP-0003610-1: Standoff, Hex, 0.5"L #4-40 Nylon; Manufacturer: Keystone; CompType: Hardware
Logo5 = CMP-0074837-2: IEC 61010-1 Hot Surface Warning; Manufacturer: Texas Instruments; SymbolCreator: a0412235; CompType: IC; AEC Category: Q200
SH-JP1-SH-JP5 = CMP-0078738-1: Single Operation 2.54mm Pitch Open Top Jumper Socket; Manufacturer: Harwin
ZZ2 = CMP-0077236-1
ZZ3 = CMP-0077237-1
ZZ4 = CMP-0077238-1

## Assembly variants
001: not fitted C4 C6 C15 C16 C30 C33 C34 C35 C36 C37 C38 C39 C40 C41 C42 D1 D2 D3 D4 FID1 FID2 FID3 FID4 FID5 FID6 H1 H2 H3 H4 H5 H6 H7 H8 J12 Q5 R22 R23 R51 R52 R53 R54 R55 R56 R57 R58 TP12 TP13 TP14 TP15 TP16 TP17 U2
